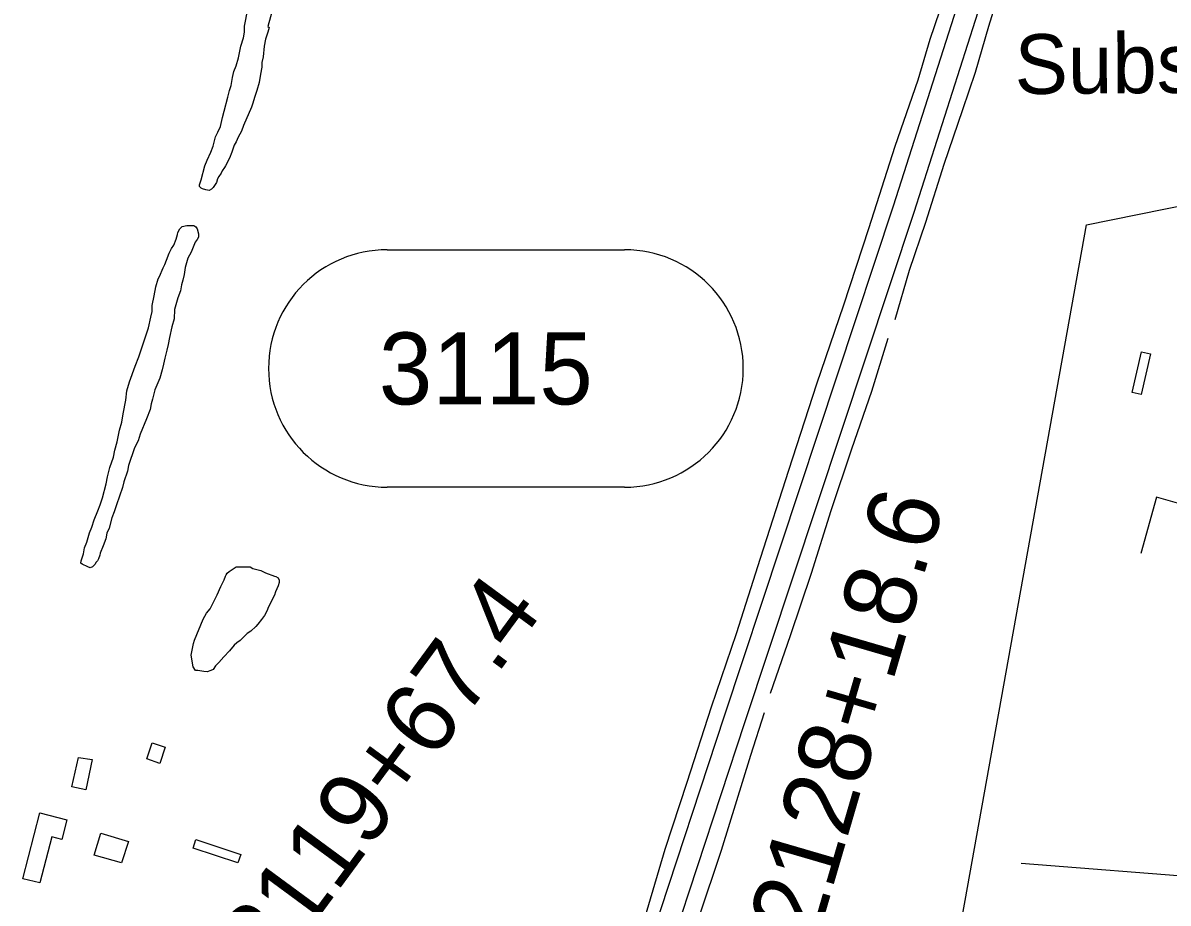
# Model space of a CAD drawing. Extents: x 3355677 to 3393573, y 612928 to 638357.
# Drawn here: x 3366481 to 3368073, y 625120 to 626343 of the extents above; entities that cross this region are included whole.
import ezdxf

# ---------------------------------------------------------------- set-up
doc = ezdxf.new("R2010")
doc.units = 0
for name, color, linetype in [('V-BLDG-OTLN', 7, 'Continuous'), ('V-ROAD-CNTR', 7, 'Continuous'), ('V-ROAD-IDEN', 7, 'Continuous'), ('V-SITE-OTLN', 7, 'Continuous'), ('V-SITE-OTLN-IDEN', 7, 'Continuous'), ('V-SITE-VEGE', 7, 'Continuous'), ('V-SURV-IDEN', 7, 'Continuous'), ('V-TOPO-SHOR', 7, 'Continuous'), ('V-UTIL-LINE', 7, 'Continuous')]:
    doc.layers.add(name, color=color, linetype=linetype)

msp = doc.modelspace()

# ---------------------------------------------------------------- linework, layer by layer
at = {"layer": 'V-BLDG-OTLN'}
for points in [[(3368049.1, 625883.2), (3368036, 625826.9), (3368023.4, 625829.8), (3368036.5, 625886.2)], [(3366653.8, 625320.5), (3366660.9, 625342.7), (3366679.1, 625336.8), (3366671.8, 625314.1)], [(3366577.8, 625319.3), (3366568.6, 625277.3), (3366549.5, 625281.4), (3366558.4, 625322.2)], [(3366481.3, 625153.9), (3366504.8, 625245.4), (3366542.6, 625235.7), (3366535.6, 625208.4), (3366521.6, 625212), (3366504.8, 625147.9)], [(3366580.3, 625186.8), (3366589.8, 625217.3), (3366627.9, 625205.4), (3366618.6, 625175.8)], [(3366721.8, 625208.2), (3366784.1, 625187.7), (3366780.3, 625176), (3366717.9, 625196.5)]]:
    msp.add_lwpolyline(points, close=True, dxfattribs=at)
at = {"layer": 'V-ROAD-CNTR'}
for points in [[(3370176.3, 633731.8), (3370097.8, 633488.5), (3369963.1, 633067.7), (3369788.9, 632536.9), (3369615.9, 632012.9), (3369499.9, 631645.2), (3369354.9, 631184.8), (3369190.9, 630657.6), (3368973.3, 629965.4), (3368863.4, 629638.7), (3368793.4, 629424.5), (3368626.8, 628928.9), (3368504.4, 628552.8), (3368323.4, 627991.2), (3368123, 627405.4), (3367929.7, 626820.3), (3367830.1, 626523.3), (3367691.3, 626088.7), (3367456.3, 625379.9), (3367356.4, 625077), (3367348, 625010)], [(3368189.4, 627506.6), (3368151.5, 627395.9), (3367958.2, 626810.8), (3367858.6, 626514), (3367719.9, 626079.5), (3367484.7, 625370.4), (3367385.8, 625070.3), (3367377.7, 625006.2)]]:
    msp.add_lwpolyline(points, dxfattribs=at)
at = {"layer": 'V-ROAD-IDEN'}
for p, q in [((3366987.8, 626028), (3367317.8, 626028)), ((3367317.8, 625698), (3366987.8, 625698))]:
    msp.add_line(p, q, dxfattribs=at)
for centre, start, end in [((3366987.8, 625863), 90, 270), ((3367317.8, 625863), 270, 90)]:
    msp.add_arc(centre, 165, start, end, dxfattribs=at)
at = {"layer": 'V-SITE-OTLN'}
msp.add_lwpolyline([(3368804.9, 624989), (3368712, 624989.9), (3367780.4, 625064.2), (3367960.1, 626062.4), (3368213.9, 626114.2), (3368483.7, 626245.1), (3369427.8, 625696.1), (3370459.1, 625066.8), (3370383.7, 624758.4), (3369690.3, 624840.8), (3369383.4, 624901)], close=True, dxfattribs=at)
at = {"layer": 'V-SITE-VEGE'}
for points in [[(3366838.2, 626397.3), (3366822, 626338.3), (3366823.7, 626336.7), (3366822, 626330.2), (3366818.6, 626320.5), (3366816.9, 626310.8), (3366815.2, 626296.2), (3366813.5, 626288.1), (3366813.4, 626281.6), (3366811.7, 626271.9), (3366810, 626260.5), (3366806.6, 626249.2), (3366803.3, 626239.5), (3366801.1, 626231.8), (3366799.1, 626226.3), (3366788.1, 626200.5), (3366785, 626192.6), (3366780.4, 626184.2), (3366777.7, 626177.8), (3366775.1, 626173.2), (3366771.8, 626163.5), (3366768.4, 626155.4), (3366763.1, 626144.7), (3366761.8, 626142.5), (3366758.5, 626137.7), (3366756.9, 626134.4), (3366753.6, 626129.6), (3366751.9, 626126.4), (3366750.3, 626121.5), (3366747.6, 626117.2), (3366745.7, 626114.5), (3366743.5, 626112.2), (3366740.4, 626110.2), (3366735.6, 626111.2), (3366730.9, 626112.7), (3366729.1, 626113.6), (3366727, 626115.7), (3366726.8, 626118.4), (3366729.2, 626124.9), (3366734.3, 626144.4), (3366737.6, 626152.5), (3366742.5, 626163.8), (3366745.9, 626171.9), (3366749.2, 626184.8), (3366752.5, 626191.3), (3366755.9, 626199.4), (3366758.6, 626211.8), (3366760.9, 626220.4), (3366766, 626239.8), (3366768.7, 626249.2), (3366771, 626256), (3366772.7, 626267.4), (3366774.4, 626275.5), (3366777.7, 626283.6), (3366781.1, 626294.9), (3366784.5, 626311.1), (3366787.8, 626322.4), (3366789.5, 626330.5), (3366789.6, 626338.6), (3366803.2, 626410.2)], [(3366720.6, 626038.3), (3366715.3, 626024.4), (3366710.4, 626016.4), (3366707, 626003.4), (3366705.3, 625993.7), (3366703.6, 625985.6), (3366701.9, 625979.1), (3366700.2, 625971), (3366696.9, 625961.3), (3366691.9, 625945.1), (3366691.7, 625932.1), (3366688.4, 625920.8), (3366685, 625906.2), (3366683.3, 625896.5), (3366681.6, 625888.4), (3366678.6, 625877.5), (3366676.6, 625869), (3366674.9, 625860.9), (3366671.5, 625849.5), (3366664.9, 625833.4), (3366661.5, 625820.4), (3366659.6, 625813.7), (3366658.1, 625805.8), (3366653.1, 625792.9), (3366644.5, 625771.5), (3366641.5, 625762.2), (3366636.5, 625752.5), (3366628.2, 625728.2), (3366626.5, 625720.1), (3366621.5, 625705.5), (3366619.8, 625697.4), (3366611.5, 625673.6), (3366608.1, 625663.5), (3366604.8, 625655.4), (3366601.4, 625640.8), (3366598.1, 625634.3), (3366596.4, 625626.2), (3366593.1, 625616.5), (3366588.9, 625606.5), (3366588.1, 625603.6), (3366586.2, 625598.6), (3366584.8, 625595.5), (3366583.2, 625593.9), (3366581.5, 625590.7), (3366578.2, 625587.4), (3366575, 625585.9), (3366571.7, 625587.5), (3366563.6, 625590.8), (3366562, 625592.5), (3366562.5, 625595.8), (3366565.4, 625605.4), (3366567.1, 625613.5), (3366570.4, 625621.6), (3366573.8, 625634.6), (3366577.1, 625642.6), (3366580.4, 625652.4), (3366585.4, 625665.3), (3366588.7, 625673.4), (3366592.1, 625683.1), (3366597.1, 625702.5), (3366598.8, 625712.2), (3366602.2, 625725.2), (3366607.2, 625739.8), (3366608.9, 625749.5), (3366612.3, 625760.8), (3366615.7, 625777), (3366619, 625788.3), (3366620.7, 625799.7), (3366624.2, 625819.1), (3366625.9, 625832.1), (3366629.7, 625844.4), (3366637.6, 625866.1), (3366642.6, 625879), (3366649.2, 625898.4), (3366652.6, 625909.8), (3366655.9, 625919.5), (3366659.3, 625934.1), (3366661, 625942.2), (3366661.1, 625950.3), (3366663.9, 625963.8), (3366666.2, 625976.2), (3366669.5, 625987.5), (3366671.2, 625990.8), (3366676.2, 626002.6), (3366678.6, 626007.5), (3366681.1, 626013.4), (3366684.5, 626023.1), (3366687.8, 626029.6), (3366691, 626034.4), (3366694.4, 626042.5), (3366696.1, 626049), (3366696.9, 626052), (3366699.4, 626057), (3366702.6, 626060.3), (3366709.2, 626061.8), (3366718.9, 626061.7), (3366721.9, 626059.8), (3366723.7, 626056.8), (3366725.3, 626050.3)], [(3366725.3, 626050.3), (3366725.2, 626045.4), (3366723.6, 626042.2), (3366720.6, 626038.3)]]:
    msp.add_lwpolyline(points, dxfattribs=at)
msp.add_lwpolyline([(3366797.3, 625587.1), (3366800.9, 625584.8), (3366811.9, 625582.1), (3366818.4, 625578.8), (3366831, 625574.5), (3366832.9, 625573.8), (3366836.2, 625572.1), (3366837.8, 625568.9), (3366837.7, 625565.6), (3366836.1, 625560.7), (3366832.7, 625552.7), (3366831.1, 625547.8), (3366822.8, 625531.7), (3366820.6, 625525.9), (3366817.3, 625519.5), (3366812.9, 625513.9), (3366808, 625507.4), (3366805.3, 625504.5), (3366798.2, 625497.8), (3366793.3, 625494.6), (3366783.4, 625484.9), (3366778.5, 625481.7), (3366775.2, 625478.5), (3366768.7, 625470.5), (3366760.5, 625462.4), (3366753.9, 625454.4), (3366749, 625449.6), (3366745.7, 625444.7), (3366742.5, 625443.1), (3366737.6, 625441.5), (3366732.7, 625441.6), (3366724.6, 625443.3), (3366721.4, 625443.3), (3366718.2, 625448.2), (3366715.1, 625464.5), (3366718.5, 625480.7), (3366719.8, 625485.3), (3366731.8, 625514.6), (3366736.7, 625522.7), (3366741.6, 625529.1), (3366751.5, 625548.5), (3366756.5, 625559.9), (3366759.8, 625566.3), (3366760.9, 625569.2), (3366763.1, 625574.4), (3366764.1, 625576.3), (3366765.5, 625578.4), (3366768.1, 625580.8), (3366777.9, 625587.2)], close=True, dxfattribs=at)
at = {"layer": 'V-TOPO-SHOR'}
for points in [[(3367742.5, 626320.5), (3367769.8, 626401.2), (3367797.2, 626488.3), (3367816.6, 626544.3), (3367839.3, 626609.1)], [(3367824.2, 626338.8), (3367863.7, 626465.9), (3367888.5, 626533.1), (3367908.3, 626591.7)], [(3367694, 625930.8), (3367713.7, 625999.6), (3367736.5, 626066.3), (3367761.9, 626146.8), (3367788, 626222.8), (3367805.8, 626274.7), (3367824.2, 626338.8)], [(3367204.7, 625010.1), (3367244.3, 625015.6), (3367283.1, 625022.5), (3367308.6, 625032), (3367318.3, 625038.8), (3367327.3, 625050.4), (3367343, 625089.8), (3367374.2, 625194.8), (3367404.9, 625288.2), (3367438.6, 625392.8), (3367473.4, 625494.6), (3367506.6, 625599.2), (3367546.1, 625721.5), (3367585.1, 625841.4), (3367622.5, 625951.6), (3367657.3, 626057.5), (3367693.9, 626171.7), (3367725.8, 626264.3), (3367742.5, 626320.5)], [(3367520.7, 625411.6), (3367548.5, 625491.8), (3367577.5, 625578.7), (3367604.9, 625665.6), (3367633.6, 625751.3), (3367661.3, 625831.4), (3367684.3, 625905.1)], [(3367585, 625028.6), (3367494.7, 625033.4), (3367446.7, 625035.5), (3367424.1, 625040.1), (3367414.5, 625043.9), (3367409.6, 625047.9), (3367408.1, 625058), (3367421, 625099.5), (3367452.5, 625193.6), (3367493.3, 625325.6), (3367512.5, 625384.8)]]:
    msp.add_lwpolyline(points, dxfattribs=at)
at = {"layer": 'V-UTIL-LINE'}
for points in [[(3368857.8, 625511.5), (3368602.6, 625591.5), (3368173.2, 625730.6), (3368148.1, 625658.2), (3368057.1, 625684.3), (3368035.3, 625606)], [(3368730, 625114.7), (3368530.8, 625128.3), (3368128.3, 625154.8), (3367869.2, 625174.9)]]:
    msp.add_lwpolyline(points, dxfattribs=at)

# ---------------------------------------------------------------- texts
at = {"layer": 'V-ROAD-IDEN'}
msp.add_text('3115', height=100, dxfattribs=at).set_placement((3366976.1, 625813))
at = {"layer": 'V-SITE-OTLN-IDEN'}
msp.add_text('Substation', height=83, rotation=0.3981, dxfattribs=at).set_placement((3367860.3, 626244.3))
at = {"layer": 'V-SURV-IDEN'}
for s, rotation, p in [('2128+18.6', 73.7264, (3367585, 625065.3)), ('2119+67.4', 53.6599, (3366829, 625013.6))]:
    msp.add_text(s, height=100, rotation=rotation, dxfattribs=at).set_placement(p)

doc.saveas('drawing.dxf')
